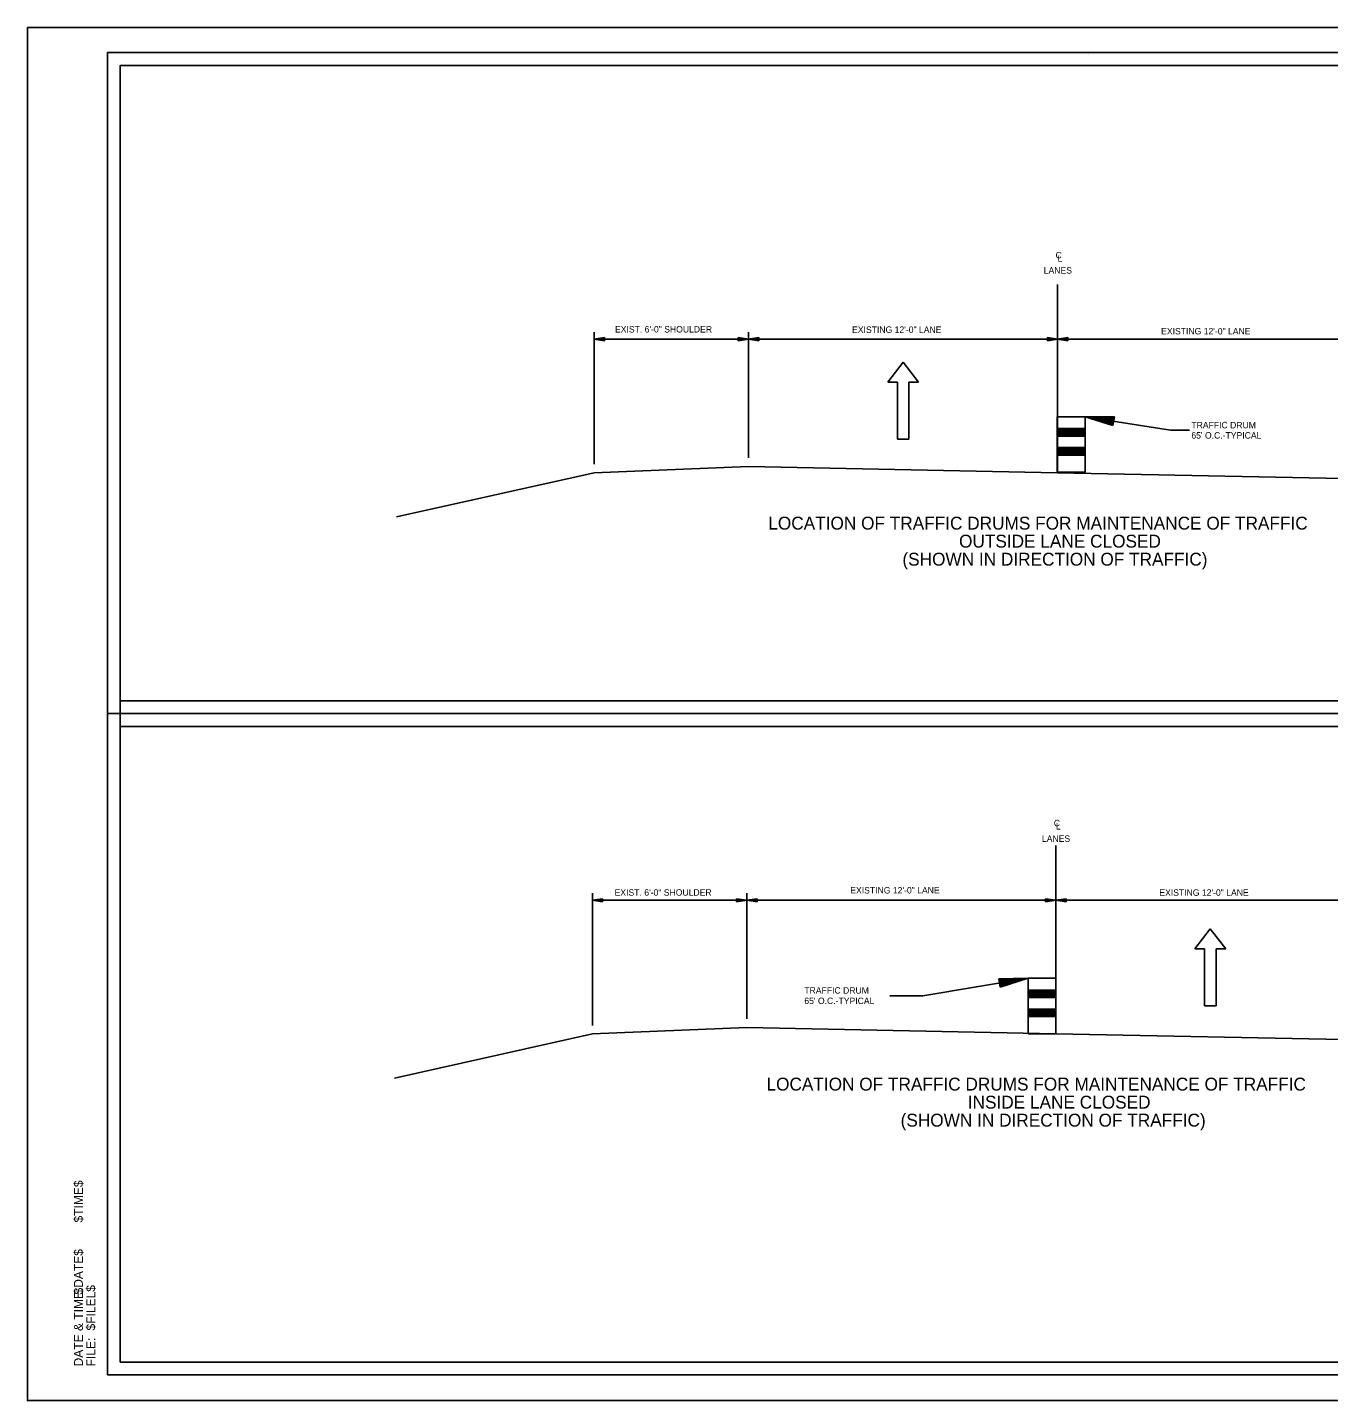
# Model space of a CAD drawing. Extents: x -500 to 213, y 382723 to 382830.
# Drawn here: x 46.8 to 147.8, y 382723.1 to 382829.8 of the extents above; entities that cross this region are included whole.
import ezdxf

# ---------------------------------------------------------------- set-up
doc = ezdxf.new("R2010")
doc.units = 0
for name, color, linetype in [('Default', 7, 'Continuous'), ('R_Border', 7, 'Continuous'), ('R_Border Notes', 7, 'Continuous'), ('R_Border Plan-Plan', 7, 'Continuous'), ('R_MOT', 7, 'Continuous'), ('R_No Plot', 7, 'Continuous'), ('R_Striping', 7, 'Continuous')]:
    doc.layers.add(name, color=color, linetype=linetype)

msp = doc.modelspace()

# ---------------------------------------------------------------- linework, layer by layer
at = {"layer": 'Default'}
for p, q in [((126.8, 382795.21), (126.8, 382809.84)), ((90.79, 382802.76), (90.79, 382806.13)), ((91.59, 382805.7), (90.79, 382805.58)), ((102.79, 382805.58), (90.79, 382805.58)), ((91.59, 382805.46), (90.79, 382805.58)), ((91.59, 382805.68), (90.92, 382805.58)), ((91.59, 382805.48), (90.92, 382805.58)), ((91.59, 382805.66), (91.06, 382805.58)), ((91.59, 382805.5), (91.06, 382805.58)), ((91.59, 382805.64), (91.19, 382805.58)), ((91.59, 382805.52), (91.19, 382805.58)), ((91.59, 382805.62), (91.33, 382805.58)), ((91.59, 382805.54), (91.33, 382805.58)), ((91.59, 382805.6), (91.47, 382805.58)), ((91.59, 382805.56), (91.47, 382805.58)), ((91.59, 382805.46), (91.59, 382805.7)), ((101.99, 382805.7), (102.79, 382805.58)), ((101.99, 382805.7), (101.99, 382805.46)), ((101.99, 382805.68), (102.66, 382805.58)), ((101.99, 382805.66), (102.52, 382805.58)), ((101.99, 382805.64), (102.39, 382805.58)), ((101.99, 382805.62), (102.25, 382805.58)), ((101.99, 382805.6), (102.12, 382805.58)), ((101.99, 382805.46), (102.79, 382805.58)), ((101.99, 382805.54), (102.25, 382805.58)), ((101.99, 382805.5), (102.52, 382805.58)), ((101.99, 382805.48), (102.66, 382805.58)), ((101.99, 382805.52), (102.39, 382805.58)), ((101.99, 382805.56), (102.12, 382805.58)), ((102.79, 382796.36), (102.79, 382806.13)), ((103.59, 382805.7), (102.79, 382805.58)), ((102.79, 382805.58), (126.8, 382805.58)), ((103.59, 382805.46), (102.79, 382805.58)), ((103.59, 382805.68), (102.93, 382805.58)), ((103.59, 382805.48), (102.93, 382805.58)), ((103.59, 382805.66), (103.07, 382805.58)), ((103.59, 382805.5), (103.07, 382805.58)), ((103.59, 382805.64), (103.2, 382805.58)), ((103.59, 382805.52), (103.2, 382805.58)), ((103.59, 382805.62), (103.33, 382805.58)), ((103.59, 382805.54), (103.33, 382805.58)), ((103.59, 382805.6), (103.47, 382805.58)), ((103.59, 382805.56), (103.47, 382805.58)), ((103.59, 382805.46), (103.59, 382805.7)), ((125.73, 382805.58), (126.8, 382805.58)), ((126, 382805.7), (126.8, 382805.58)), ((126, 382805.7), (126, 382805.46)), ((126, 382805.68), (126.66, 382805.58)), ((126, 382805.66), (126.53, 382805.58)), ((126, 382805.64), (126.39, 382805.58)), ((126, 382805.62), (126.26, 382805.58)), ((126, 382805.6), (126.12, 382805.58)), ((126, 382805.46), (126.8, 382805.58)), ((126, 382805.54), (126.26, 382805.58)), ((126, 382805.5), (126.53, 382805.58)), ((126, 382805.48), (126.66, 382805.58)), ((126, 382805.52), (126.39, 382805.58)), ((126, 382805.56), (126.12, 382805.58)), ((127.6, 382805.7), (126.8, 382805.58)), ((126.8, 382805.58), (150.8, 382805.58)), ((127.6, 382805.46), (126.8, 382805.58)), ((127.6, 382805.68), (126.93, 382805.58)), ((127.6, 382805.48), (126.93, 382805.58)), ((127.6, 382805.66), (127.07, 382805.58)), ((127.6, 382805.5), (127.07, 382805.58)), ((127.6, 382805.64), (127.2, 382805.58)), ((127.6, 382805.52), (127.2, 382805.58)), ((127.6, 382805.62), (127.34, 382805.58)), ((127.6, 382805.54), (127.34, 382805.58)), ((127.6, 382805.6), (127.47, 382805.58)), ((127.6, 382805.56), (127.47, 382805.58)), ((127.6, 382805.46), (127.6, 382805.7)), ((90.79, 382795.86), (90.79, 382802.76)), ((128.93, 382799.56), (135.56, 382798.52)), ((135.56, 382798.52), (137.04, 382798.52)), ((90.79, 382795.21), (75.43, 382791.77)), ((102.79, 382795.69), (90.79, 382795.21)), ((126.8, 382795.21), (102.79, 382795.69)), ((150.8, 382794.73), (126.8, 382795.21)), ((126.66, 382751.62), (126.66, 382766.26)), ((90.65, 382759.18), (90.65, 382762.54)), ((91.45, 382762.11), (90.65, 382761.99)), ((102.65, 382761.99), (90.65, 382761.99)), ((91.45, 382761.87), (90.65, 382761.99)), ((91.45, 382762.09), (90.79, 382761.99)), ((91.45, 382761.89), (90.79, 382761.99)), ((91.45, 382762.07), (90.92, 382761.99)), ((91.45, 382761.91), (90.92, 382761.99)), ((91.45, 382762.05), (91.06, 382761.99)), ((91.45, 382761.93), (91.06, 382761.99)), ((91.45, 382762.03), (91.19, 382761.99)), ((91.45, 382761.95), (91.19, 382761.99)), ((91.45, 382762.01), (91.33, 382761.99)), ((91.45, 382761.97), (91.33, 382761.99)), ((91.45, 382761.87), (91.45, 382762.11)), ((101.85, 382762.11), (102.65, 382761.99)), ((101.85, 382762.11), (101.85, 382761.87)), ((101.85, 382762.09), (102.52, 382761.99)), ((101.85, 382762.07), (102.38, 382761.99)), ((101.85, 382762.05), (102.25, 382761.99)), ((101.85, 382762.03), (102.11, 382761.99)), ((101.85, 382762.01), (101.98, 382761.99)), ((101.85, 382761.87), (102.65, 382761.99)), ((101.85, 382761.95), (102.11, 382761.99)), ((101.85, 382761.91), (102.38, 382761.99)), ((101.85, 382761.89), (102.52, 382761.99)), ((101.85, 382761.93), (102.25, 382761.99)), ((101.85, 382761.97), (101.98, 382761.99)), ((102.65, 382752.77), (102.65, 382762.54)), ((103.46, 382762.11), (102.65, 382761.99)), ((102.65, 382761.99), (126.66, 382761.99)), ((103.46, 382761.87), (102.65, 382761.99)), ((103.46, 382762.09), (102.79, 382761.99)), ((103.46, 382761.89), (102.79, 382761.99)), ((103.46, 382762.07), (102.93, 382761.99)), ((103.46, 382761.91), (102.93, 382761.99)), ((103.46, 382762.05), (103.06, 382761.99)), ((103.46, 382761.93), (103.06, 382761.99)), ((103.46, 382762.03), (103.2, 382761.99)), ((103.46, 382761.95), (103.2, 382761.99)), ((103.46, 382762.01), (103.33, 382761.99)), ((103.46, 382761.97), (103.33, 382761.99)), ((103.46, 382761.87), (103.46, 382762.11)), ((125.59, 382761.99), (126.66, 382761.99)), ((125.86, 382762.11), (126.66, 382761.99)), ((125.86, 382762.11), (125.86, 382761.87)), ((125.86, 382762.09), (126.53, 382761.99)), ((125.86, 382762.07), (126.39, 382761.99)), ((125.86, 382762.05), (126.26, 382761.99)), ((125.86, 382762.03), (126.12, 382761.99)), ((125.86, 382762.01), (125.99, 382761.99)), ((125.86, 382761.87), (126.66, 382761.99)), ((125.86, 382761.95), (126.12, 382761.99)), ((125.86, 382761.91), (126.39, 382761.99)), ((125.86, 382761.89), (126.53, 382761.99)), ((125.86, 382761.93), (126.26, 382761.99)), ((125.86, 382761.97), (125.99, 382761.99)), ((127.46, 382762.11), (126.66, 382761.99)), ((126.66, 382761.99), (150.66, 382761.99)), ((127.46, 382761.87), (126.66, 382761.99)), ((127.46, 382762.09), (126.79, 382761.99)), ((127.46, 382761.89), (126.79, 382761.99)), ((127.46, 382762.07), (126.93, 382761.99)), ((127.46, 382761.91), (126.93, 382761.99)), ((127.46, 382762.05), (127.06, 382761.99)), ((127.46, 382761.93), (127.06, 382761.99)), ((127.46, 382762.03), (127.2, 382761.99)), ((127.46, 382761.95), (127.2, 382761.99)), ((127.46, 382762.01), (127.33, 382761.99)), ((127.46, 382761.97), (127.33, 382761.99)), ((127.46, 382761.87), (127.46, 382762.11)), ((90.65, 382752.27), (90.65, 382759.18)), ((116.33, 382754.57), (124.5, 382755.94)), ((113.77, 382754.57), (116.33, 382754.57)), ((90.65, 382751.62), (75.29, 382748.18)), ((102.65, 382752.1), (90.65, 382751.62)), ((126.66, 382751.62), (102.65, 382752.1)), ((150.66, 382751.14), (126.66, 382751.62))]:
    msp.add_line(p, q, dxfattribs=at)
at = {"layer": 'R_Border'}
for p, q in [((52.97, 382827.85), (211.06, 382827.85)), ((52.97, 382725.12), (52.97, 382827.85)), ((129.23, 382827.72), (129.23, 382827.72)), ((129.23, 382827.72), (129.23, 382827.72)), ((52.97, 382725.12), (52.97, 382725.12)), ((211.06, 382725.12), (52.97, 382725.12))]:
    msp.add_line(p, q, dxfattribs=at)
at = {"layer": 'R_Border Plan-Plan'}
msp.add_line((52.97, 382776.49), (211.06, 382776.49), dxfattribs=at)
at = {"layer": 'R_MOT'}
for p, q in [((131.1, 382798.88), (128.93, 382799.56)), ((131.21, 382799.55), (128.93, 382799.56)), ((131.11, 382798.94), (129.3, 382799.51)), ((131.2, 382799.49), (129.3, 382799.51)), ((131.19, 382799.44), (129.68, 382799.45)), ((131.12, 382798.99), (129.68, 382799.45)), ((131.13, 382799.05), (130.05, 382799.39)), ((131.18, 382799.38), (130.05, 382799.39)), ((131.17, 382799.32), (130.43, 382799.33)), ((131.14, 382799.11), (130.43, 382799.33)), ((131.16, 382799.27), (130.8, 382799.27)), ((131.15, 382799.16), (130.8, 382799.27)), ((131.1, 382798.88), (131.21, 382799.55)), ((126.77, 382798.64), (128.93, 382798.64)), ((126.77, 382798.56), (128.93, 382798.56)), ((126.77, 382798.48), (128.93, 382798.48)), ((126.77, 382798.41), (128.93, 382798.41)), ((126.77, 382798.32), (128.93, 382798.32)), ((126.77, 382798.22), (128.93, 382798.22)), ((126.77, 382798.12), (128.93, 382798.12)), ((126.77, 382798.06), (128.93, 382798.06)), ((126.77, 382797.16), (128.93, 382797.16)), ((126.77, 382797.08), (128.93, 382797.08)), ((126.77, 382797), (128.93, 382797)), ((126.77, 382796.93), (128.93, 382796.93)), ((126.77, 382796.84), (128.93, 382796.84)), ((126.77, 382796.74), (128.93, 382796.74)), ((126.77, 382796.64), (128.93, 382796.64)), ((126.77, 382796.58), (128.93, 382796.58)), ((122.22, 382755.9), (124.5, 382755.94)), ((122.22, 382755.9), (122.34, 382755.24)), ((122.23, 382755.85), (124.13, 382755.88)), ((122.24, 382755.79), (123.75, 382755.82)), ((122.25, 382755.74), (123.38, 382755.76)), ((122.26, 382755.68), (123, 382755.69)), ((122.27, 382755.62), (122.63, 382755.63)), ((122.29, 382755.52), (122.63, 382755.63)), ((122.3, 382755.46), (123, 382755.69)), ((122.31, 382755.41), (123.38, 382755.76)), ((122.32, 382755.35), (123.75, 382755.82)), ((122.33, 382755.29), (124.13, 382755.88)), ((122.34, 382755.24), (124.5, 382755.94)), ((124.5, 382755.02), (126.66, 382755.02)), ((124.5, 382754.94), (126.66, 382754.94)), ((124.5, 382754.86), (126.66, 382754.86)), ((124.5, 382754.79), (126.66, 382754.79)), ((124.5, 382754.7), (126.66, 382754.7)), ((124.5, 382754.6), (126.66, 382754.6)), ((124.5, 382754.5), (126.66, 382754.5)), ((124.5, 382754.44), (126.66, 382754.44)), ((124.5, 382753.54), (126.66, 382753.54)), ((124.5, 382753.46), (126.66, 382753.46)), ((124.5, 382753.38), (126.66, 382753.38)), ((124.5, 382753.31), (126.66, 382753.31)), ((124.5, 382753.22), (126.66, 382753.22)), ((124.5, 382753.12), (126.66, 382753.12)), ((124.5, 382753.02), (126.66, 382753.02)), ((124.5, 382752.96), (126.66, 382752.96))]:
    msp.add_line(p, q, dxfattribs=at)
for points in [[(126.77, 382799.56), (128.93, 382799.56), (128.93, 382795.24), (126.77, 382795.24)], [(124.5, 382755.94), (126.66, 382755.94), (126.66, 382751.62), (124.5, 382751.62)]]:
    msp.add_lwpolyline(points, close=True, dxfattribs=at)
at = {"layer": 'R_No Plot'}
for points in [[(46.76, 382829.8), (213.43, 382829.8), (213.43, 382723.13), (46.76, 382723.13)], [(210.06, 382777.49), (53.97, 382777.49), (53.97, 382826.85), (178.74, 382826.85), (178.74, 382821.91), (187.51, 382821.91), (199.56, 382821.91), (199.56, 382810.74), (210.06, 382810.74)], [(53.97, 382826.85), (178.74, 382826.85), (178.74, 382821.91), (187.51, 382821.91), (199.56, 382821.91), (199.56, 382810.74), (210.06, 382810.74), (210.06, 382726.12), (53.97, 382726.12)], [(53.97, 382775.49), (210.06, 382775.49), (210.06, 382726.12), (53.97, 382726.12)]]:
    msp.add_lwpolyline(points, close=True, dxfattribs=at)
at = {"layer": 'R_Striping'}
for p, q in [((113.6, 382802.23), (114.8, 382803.79)), ((114.8, 382803.79), (116, 382802.23)), ((113.6, 382802.23), (114.35, 382802.23)), ((114.35, 382802.23), (114.35, 382797.82)), ((115.25, 382802.23), (115.25, 382797.82)), ((115.25, 382802.23), (116, 382802.23)), ((114.35, 382797.82), (115.25, 382797.82)), ((137.46, 382758.21), (138.66, 382759.77)), ((138.66, 382759.77), (139.86, 382758.21)), ((137.46, 382758.21), (138.21, 382758.21)), ((138.21, 382758.21), (138.21, 382753.8)), ((139.11, 382758.21), (139.11, 382753.8)), ((139.11, 382758.21), (139.86, 382758.21)), ((138.21, 382753.8), (139.11, 382753.8))]:
    msp.add_line(p, q, dxfattribs=at)

# ---------------------------------------------------------------- texts
at = {"layer": 'Default'}
for s, height, p in [('C', 0.5, (126.64, 382811.86)), ('L', 0.5, (126.8, 382811.6)), ('LANES', 0.5, (125.72, 382810.68)), ('EXIST. 6\'-0" SHOULDER', 0.5001, (92.41, 382806.1)), ('EXISTING 12\'-0" LANE', 0.5001, (110.83, 382806.07)), ('EXISTING 12\'-0" LANE', 0.5001, (134.84, 382805.95)), ('LOCATION OF TRAFFIC DRUMS FOR MAINTENANCE OF TRAFFIC', 1.0002, (104.32, 382790.79)), ('OUTSIDE LANE CLOSED', 1.0002, (119.14, 382789.39)), ('(SHOWN IN DIRECTION OF TRAFFIC)', 1.0002, (114.74, 382787.99)), ('C', 0.5, (126.5, 382767.74)), ('L', 0.5, (126.66, 382767.49)), ('LANES', 0.5, (125.58, 382766.53)), ('EXIST. 6\'-0" SHOULDER', 0.5001, (92.38, 382762.35)), ('EXISTING 12\'-0" LANE', 0.5001, (110.69, 382762.52)), ('EXISTING 12\'-0" LANE', 0.5001, (134.7, 382762.34)), ('LOCATION OF TRAFFIC DRUMS FOR MAINTENANCE OF TRAFFIC', 1.0002, (104.18, 382747.21)), ('INSIDE LANE CLOSED', 1.0002, (119.82, 382745.81)), ('(SHOWN IN DIRECTION OF TRAFFIC)', 1.0002, (114.6, 382744.41))]:
    msp.add_text(s, height=height, dxfattribs=at).set_placement(p)
for s, p in [('TRAFFIC DRUM', (137.19, 382798.66)), ("65' O.C.-TYPICAL", (137.19, 382797.86)), ('TRAFFIC DRUM', (107.12, 382754.74)), ("65' O.C.-TYPICAL", (107.12, 382753.93))]:
    msp.add_text(s, height=0.5001, rotation=360, dxfattribs=at).set_placement(p)
at = {"layer": 'R_Border Notes'}
for s, height, p in [('$TIME$', 0.698, (51.07, 382736.96)), ('$DATE$', 0.698, (51.07, 382731.37)), ('$FILEL$', 0.698, (52.03, 382728.57)), ('DATE & TIME:', 0.6984, (51.07, 382725.78)), ('FILE: ', 0.698, (52.03, 382725.78))]:
    msp.add_text(s, height=height, rotation=90, dxfattribs=at).set_placement(p)

doc.saveas('drawing.dxf')
